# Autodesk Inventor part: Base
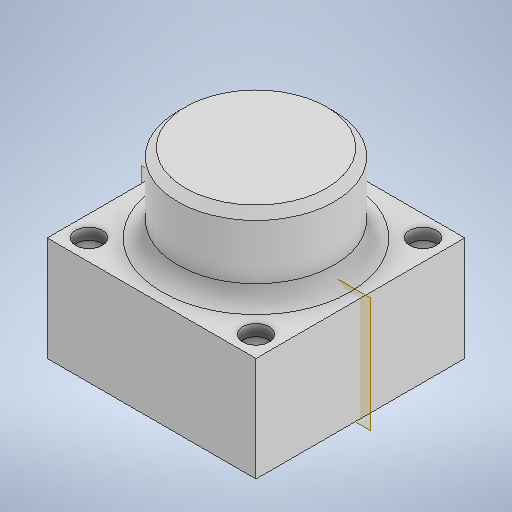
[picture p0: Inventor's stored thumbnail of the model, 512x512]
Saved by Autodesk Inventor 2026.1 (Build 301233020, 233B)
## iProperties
Created: 2026-11
Part Number: Base
Material: Generic
Document SubType Name: Modeling
Designer: hp
Density: 1 g/cm^3
Appearance: Default
Author: hp
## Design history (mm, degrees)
sketch "Sketch1"
  geometry: L1 (-20, 20)-(20, 20); L2 (20, 20)-(20, -20); L3 (20, -20)-(-20, -20); L4 (-20, -20)-(-20, 20); L5 (-20, 20)-(20, -20); L6 (20, 20)-(-20, -20); C1 r 10 at (0, 0); 1 further point
  constraints: 12 end point, 2 midpoint, 2 parallel, 1 centre point, 1 coincident, 1 horizontal, 1 perpendicular
  dimensions: "d0" = 40 distance of L2.end L3.end; "d1" = 40 distance of L1.end L2.end; "d2" = 20 diameter of C1
extrude "Extrusion1" new body sketch "Sketch1" distance "d3" = 20; taper "d4" = 0 deg
workplane "Work Plane1"
sketch "Sketch3"
  geometry: L1 (0, 0)-(40, 0) reference; L2 (40, 0)-(40, 20) reference; L3 (0, 20)-(40, 20) reference; L4 (0, 0)-(0, 20) reference; L5 (20, 20)-(20, 35); L6 (20, 35)-(35, 35); L7 (35, 35)-(35, 20); L8 (20, 20)-(35, 20); 1 further point
  constraints: 8 end point, 2 perpendicular, 1 collinear, 1 midpoint, 1 point on line, 1 vertical
  dimensions: "d8" = 15 distance of L5.start L5.end; "d9" = 15 distance of L5.end L6.end
revolve "Revolution2" sketch "Sketch3" stored, may be unused: angle "d10" = 360 deg
fillet "Fillet1" dims "d11" = 3
chamfer "Chamfer1" distance "d12" = 1.5; stored, may be unused: second distance "d13" = 2, angle "d14" = 45 deg
sketch "Sketch6"
  geometry: L1 (20, 20)-(-20, 20) reference; L2 (-20, 20)-(-20, -20) reference; L3 (-20, -20)-(20, -20) reference; L4 (20, -20)-(20, 20) reference; L5 (0, -20)-(0, 20); L6 (-20, 0)-(20, 0); C1 r 18 at (0, 0) reference; C2 r 2.55 at (-16, 16); C3 r 2.55 at (16, 16); C4 r 2.55 at (-16, -16); C5 r 2.55 at (16, -16); 1 further point
  constraints: 4 centre point, 4 end point, 4 midpoint, 3 symmetric about line, 3 other
  dimensions: "d19" = 5.1 diameter of C2; "d20" = 4 distance from line of L2 C2.centre; "d21" = 4 distance from line of C2.centre L1 (= d20)
extrude "Extrusion3" cut sketch "Sketch6" stored distance "d22" = 2.2; taper "d23" = 0 deg
body "Solid1"
node "Projected Loop1"
node "Projected Loop4"
